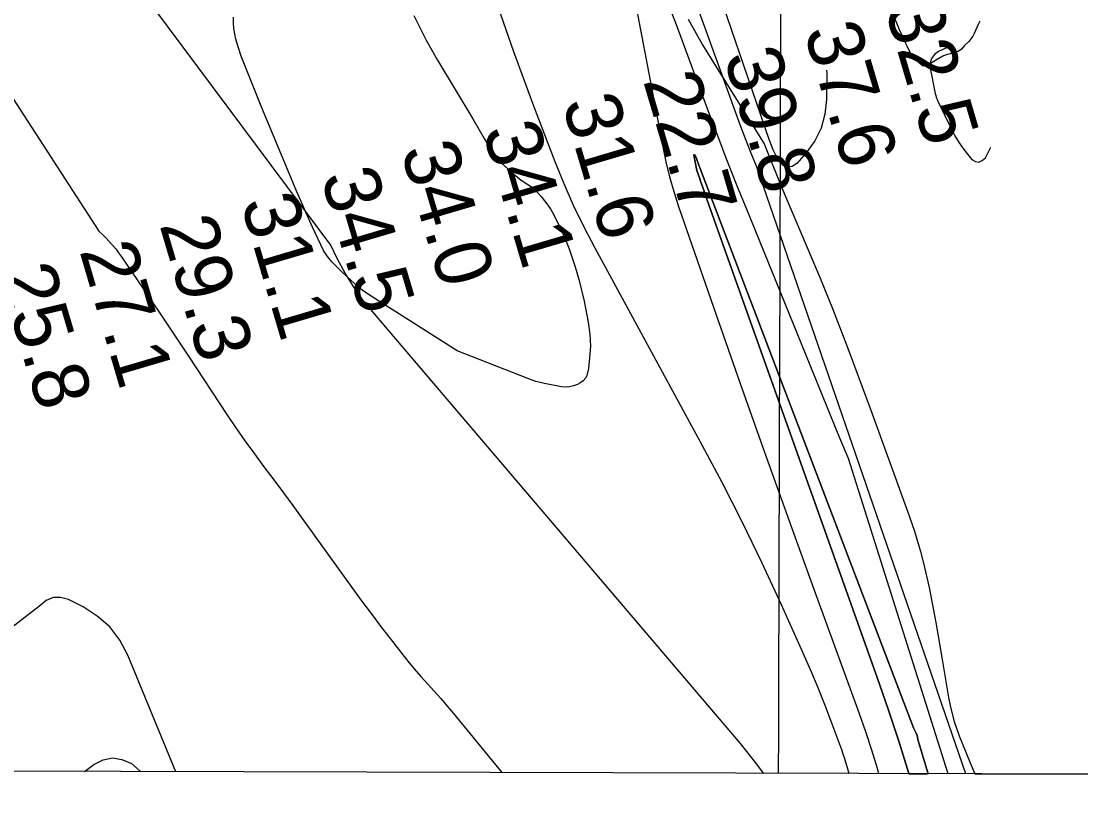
# Model space of a CAD drawing. Extents: x 3161665 to 3199565, y 885729 to 911164.
# Drawn here: x 3180653 to 3181912, y 891109 to 892047 of the extents above; entities that cross this region are included whole.
import ezdxf

# ---------------------------------------------------------------- set-up
doc = ezdxf.new("R2010")
doc.units = 0
for name, color, linetype in [('V-GRID-FRAM', 7, 'Continuous'), ('V-GRID-MAJR', 7, 'Continuous'), ('V-RIVR-RANG', 7, 'Continuous'), ('V-SITE-VEGE', 7, 'Continuous'), ('V-TOPO-DPTH', 7, 'Continuous'), ('V-TOPO-MAJR', 7, 'Continuous'), ('V-TOPO-MINR', 7, 'Continuous'), ('V-TOPO-SHOR', 7, 'Continuous')]:
    doc.layers.add(name, color=color, linetype=linetype)

msp = doc.modelspace()

# ---------------------------------------------------------------- linework, layer by layer
at = {"layer": 'V-GRID-FRAM'}
msp.add_lwpolyline([(3165935.6, 909383.8), (3197271.3, 909297.2), (3197229, 891108.8), (3165877.4, 891195.5), (3165935.6, 909383.8)], dxfattribs=at)
at = {"layer": 'V-GRID-MAJR'}
msp.add_spline([(3181553.2, 891152.2), (3181570, 897211.5), (3181586.7, 903274.3), (3181603.5, 909337.1), (3181603.5, 909340.5)], degree=3, dxfattribs=at)
at = {"layer": 'V-SITE-VEGE'}
for p, q in [((3181693.8, 892044.4), (3181688.8, 892055.5)), ((3181445.5, 892049.3), (3181462.5, 892018.8)), ((3181697.9, 892034.4), (3181693.8, 892044.4)), ((3181790.1, 892042.2), (3181786.1, 892032.9)), ((3181792.5, 892046.9), (3181790.1, 892042.2)), ((3181701.5, 892026.9), (3181697.9, 892034.4)), ((3181703.2, 892023.6), (3181701.5, 892026.9)), ((3181784, 892029), (3181779.4, 892022.7)), ((3181786.1, 892032.9), (3181784, 892029)), ((3181462.5, 892018.8), (3181472.9, 892001.8)), ((3181704.4, 892020.3), (3181703.2, 892023.6)), ((3181705.9, 892017), (3181704.4, 892020.3)), ((3181710, 892008.9), (3181705.9, 892017)), ((3181774.3, 892017.7), (3181770.7, 892013.5)), ((3181779.4, 892022.7), (3181774.3, 892017.7)), ((3181472.9, 892001.8), (3181536.1, 891901)), ((3181712.4, 892005.8), (3181710, 892008.9)), ((3181714.5, 892002.8), (3181712.4, 892005.8)), ((3181717.8, 891999.2), (3181714.5, 892002.8)), ((3181748.4, 892005), (3181740.9, 892000.8)), ((3181751.4, 892006.4), (3181748.4, 892005)), ((3181757.1, 892007.9), (3181751.4, 892006.4)), ((3181760.1, 892009.1), (3181757.1, 892007.9)), ((3181766.8, 892010.8), (3181760.1, 892009.1)), ((3181770.7, 892013.5), (3181766.8, 892010.8)), ((3181721.3, 891995.9), (3181717.8, 891999.2)), ((3181724.9, 891993.4), (3181721.3, 891995.9)), ((3181729.4, 891994.3), (3181724.9, 891993.4)), ((3181732.7, 891995.5), (3181729.4, 891994.3)), ((3181740.9, 892000.8), (3181732.7, 891995.5)), ((3181536.1, 891901), (3181557.2, 891848.5)), ((3181557.2, 891848.5), (3181602.6, 891741.1)), ((3181602.6, 891741.1), (3181617.1, 891705)), ((3181617.1, 891705), (3181635.7, 891656.8)), ((3181635.7, 891656.8), (3181662.8, 891584)), ((3181662.8, 891584), (3181706.5, 891464)), ((3181706.5, 891464), (3181714.6, 891440.3)), ((3181714.6, 891440.3), (3181721.9, 891416.2)), ((3181721.9, 891416.2), (3181726, 891400.6)), ((3181726, 891400.6), (3181732.2, 891373.1)), ((3181732.2, 891373.1), (3181740, 891331.6)), ((3181740, 891331.6), (3181747.2, 891290)), ((3181747.2, 891290), (3181755, 891242.3)), ((3181755, 891242.3), (3181757.5, 891230.8)), ((3181757.5, 891230.8), (3181762.1, 891213.7)), ((3181762.1, 891213.7), (3181767.9, 891197)), ((3181767.9, 891197), (3181780.8, 891164.8)), ((3181780.8, 891164.8), (3181786.4, 891151.5)), ((3181786.4, 891151.5), (3182625.4, 891149.2))]:
    msp.add_line(p, q, dxfattribs=at)
for points in [[(3181119.6, 892053.6), (3181127.2, 892037.7), (3181134.3, 892024), (3181147.7, 892000.4)], [(3181322.1, 891713.8), (3181326.9, 891688.7), (3181328.8, 891674.6), (3181329.4, 891660.4), (3181328.9, 891651.2), (3181328.1, 891642), (3181327.1, 891633.7), (3181325.1, 891625.4), (3181323.8, 891622.7), (3181320.8, 891619.2), (3181316.9, 891616.3), (3181313.9, 891614.6), (3181309.3, 891612.9), (3181304.6, 891611.9), (3181299.7, 891611.5), (3181294.9, 891611.7), (3181274.7, 891615.7), (3181264.7, 891618.3), (3181255, 891621.7), (3181171.1, 891654.9), (3181064.4, 891722.5), (3181056.2, 891728.3), (3181044.9, 891738.3), (3181034, 891748.8), (3181022, 891760.6), (3181016.7, 891767), (3181012.2, 891774.1), (3180998.8, 891801.8), (3180980.2, 891843.8), (3180938.1, 891945.5), (3180914.3, 892005.1), (3180910.9, 892015.1), (3180908, 892025.3), (3180906.6, 892031.6), (3180905.6, 892037.9), (3180905.1, 892044.7), (3180905, 892051.6)], [(3181147.7, 892000.4), (3181189.8, 891930.7), (3181203.2, 891907.3), (3181210.3, 891895.7), (3181217.9, 891884.5), (3181223.8, 891878), (3181238.4, 891864.7), (3181246.9, 891857.6), (3181260.5, 891849), (3181265.9, 891843.8), (3181270.8, 891838.1), (3181278.6, 891828), (3181282.2, 891822.8), (3181285.4, 891817.2), (3181293.1, 891801.7), (3181299.2, 891788.1), (3181304, 891776), (3181311.4, 891754.7), (3181316.1, 891738.5), (3181322.1, 891713.8)]]:
    msp.add_lwpolyline(points, dxfattribs=at)
at = {"layer": 'V-TOPO-DPTH'}
for points in [[(3181462.6, 891850), (3181460.8, 891855.3), (3181459, 891860.6), (3181456.1, 891869.1), (3181455.5, 891871.2), (3181455, 891873.3), (3181452.3, 891887.5), (3181452.5, 891887.8), (3181452.7, 891888.1), (3181452.9, 891888), (3181453.3, 891887.8), (3181454, 891886.5), (3181455.4, 891883.7), (3181456, 891882.2), (3181458.9, 891874.5), (3181459.3, 891873.5), (3181460.1, 891871.4), (3181460.5, 891870.3), (3181713.7, 891206.5), (3181714.1, 891205.7), (3181714.7, 891204.1), (3181716.6, 891200.1), (3181718, 891197.2), (3181718.4, 891195.3), (3181718.9, 891192.3), (3181719.9, 891188.4), (3181730.9, 891151.7)], [(3181730.9, 891151.7), (3181719.9, 891188.4), (3181718.9, 891192.3), (3181718.4, 891195.3), (3181718, 891197.2), (3181716.6, 891200.1), (3181714.7, 891204.1), (3181714.1, 891205.7), (3181713.7, 891206.5), (3181460.5, 891870.3), (3181460.1, 891871.4), (3181459.3, 891873.5), (3181458.9, 891874.5), (3181456, 891882.2), (3181455.4, 891883.7), (3181454, 891886.5), (3181453.3, 891887.8), (3181452.9, 891888), (3181452.7, 891888.1), (3181452.5, 891887.8), (3181452.3, 891887.5), (3181455, 891873.3), (3181455.5, 891871.2), (3181456.1, 891869.1), (3181459, 891860.6), (3181460.8, 891855.3), (3181462.6, 891850)], [(3181730.9, 891151.7), (3181708, 891151.7), (3181707.9, 891152), (3181696.1, 891190.3), (3181683.6, 891228.4), (3181670.5, 891266.3), (3181466.3, 891839.5), (3181464.5, 891844.7), (3181462.6, 891850)], [(3181462.6, 891850), (3181464.5, 891844.7), (3181466.3, 891839.5), (3181670.5, 891266.3), (3181683.6, 891228.4), (3181696.1, 891190.3), (3181707.9, 891152), (3181708, 891151.7), (3181730.9, 891151.7)]]:
    msp.add_lwpolyline(points, dxfattribs=at)
at = {"layer": 'V-TOPO-MAJR'}
msp.add_lwpolyline([(3181610.3, 891988.4), (3181610.4, 891985.1), (3181610.2, 891953.5), (3181608.2, 891936.1), (3181603.9, 891919.6), (3181596.1, 891904.3), (3181586, 891890), (3181575, 891877.4), (3181569.1, 891874.1), (3181563.5, 891873.1), (3181558.3, 891875.5), (3181553.5, 891880.3), (3181548.8, 891889.9), (3181546.9, 891893.9), (3181545.1, 891897.9), (3181543.5, 891902), (3181542, 891906.2), (3181367, 892416.9), (3181343.1, 892486.4), (3181319.1, 892555.9)], dxfattribs=at)
at = {"layer": 'V-TOPO-MINR'}
for points in [[(3181775.7, 891151.5), (3181526.9, 891874.2), (3181520.2, 891890.5), (3181513.8, 891906.9), (3181507.6, 891923.4), (3181421.8, 892160.7), (3181395.1, 892231.3), (3181147.5, 892778.3)], [(3181535.8, 891152.2), (3181525.7, 891165), (3181507.9, 891187.8), (3181070.4, 891701.4), (3181058.4, 891715.9), (3181047.7, 891731.3), (3181037.7, 891747.1), (3181028.8, 891763.6), (3181020.6, 891780.5), (3180544.9, 892418.5)], [(3180363.9, 892385.2), (3180744.9, 891797.1), (3180749.1, 891793), (3180753.3, 891788.9), (3180757.3, 891784.7), (3180761.2, 891780.4), (3180765, 891776), (3180768.5, 891771.3), (3180771.9, 891766.6), (3180803.8, 891719.5), (3180815.7, 891701.7), (3180827.7, 891684), (3180839.5, 891666.1), (3180851.4, 891648.3), (3180897.1, 891579.1), (3180907.8, 891563.3), (3180918.7, 891547.6), (3180929.9, 891532.1), (3180941.3, 891516.7), (3180952.8, 891501.4), (3180964.3, 891486), (3180975.6, 891470.6), (3180986.8, 891455.1), (3181043.9, 891376), (3181056.2, 891359.1), (3181068.6, 891342.3), (3181081.2, 891325.7), (3181094, 891309.1), (3181105.1, 891294.7), (3181112.5, 891285.5), (3181120, 891276.4), (3181127.7, 891267.5), (3181135.6, 891258.8), (3181143.6, 891250.1), (3181151.4, 891241.3)], [(3181370.7, 892132.6), (3181415.4, 891897.4), (3181419.2, 891879.5), (3181423.6, 891861.6), (3181428.7, 891844), (3181434.3, 891826.5), (3181479, 891697.6), (3181507.6, 891615.8), (3181536.4, 891534.1), (3181565.7, 891452.6), (3181595.1, 891371.1), (3181648.9, 891223.4), (3181656.5, 891201.8), (3181663.7, 891180.1), (3181670.3, 891158.2), (3181672.1, 891151.8)], [(3181216.5, 892072.5), (3181238, 892010.7), (3181260.5, 891949.3), (3181287, 891880), (3181297.7, 891853.7), (3181309, 891827.8), (3181321.4, 891802.3), (3181334.5, 891777.1), (3181459.7, 891547.2), (3181485.1, 891499.3), (3181509.7, 891451.1), (3181533.3, 891402.4), (3181556.1, 891353.2), (3181582.1, 891295.5), (3181591.1, 891274.9), (3181599.8, 891254.2), (3181608.1, 891233.3), (3181616.2, 891212.2), (3181627.8, 891180.7), (3181629.7, 891175.3), (3181631.5, 891169.9), (3181633.2, 891164.5), (3181634.7, 891159), (3181636.6, 891151.9)], [(3181754.9, 891151.6), (3181636.1, 891526.8), (3181625.8, 891550.9), (3181515.7, 891821.9), (3181503.7, 891851.9), (3181491.8, 891882), (3181480.2, 891912.3), (3181468.8, 891942.5), (3181430.6, 892045.6), (3181421, 892069.5)], [(3181756.3, 892016.7), (3181743.3, 892010.7), (3181738.4, 892007), (3181734.8, 892002.5), (3181733.4, 891997), (3181733.3, 891990.8), (3181739.5, 891960.8), (3181740, 891958.5), (3181740.7, 891956.2), (3181742.5, 891951.8), (3181758.2, 891919), (3181762.7, 891910.3), (3181767.7, 891902), (3181773.4, 891894.1), (3181779.5, 891886.5), (3181783, 891882.4), (3181787.3, 891879.9), (3181791.4, 891879.1), (3181795.3, 891880.9), (3181799, 891884.3), (3181805.6, 891896.8)], [(3181462.6, 891850), (3181460.8, 891855.3), (3181459, 891860.6), (3181456.1, 891869.1), (3181455.5, 891871.2), (3181455, 891873.3), (3181452.3, 891887.5), (3181452.5, 891887.8), (3181452.7, 891888.1), (3181452.9, 891888), (3181453.3, 891887.8), (3181454, 891886.5), (3181455.4, 891883.7), (3181456, 891882.2), (3181458.9, 891874.5), (3181459.3, 891873.5), (3181460.1, 891871.4), (3181460.5, 891870.3), (3181713.7, 891206.5), (3181714.1, 891205.7), (3181714.7, 891204.1), (3181716.6, 891200.1), (3181718, 891197.2), (3181718.4, 891195.3), (3181718.9, 891192.3), (3181719.9, 891188.4), (3181730.9, 891151.7)], [(3181708, 891151.7), (3181707.9, 891152), (3181696.1, 891190.3), (3181683.6, 891228.4), (3181670.5, 891266.3), (3181466.3, 891839.5), (3181464.5, 891844.7), (3181462.6, 891850)], [(3180836.6, 891154.1), (3180779.5, 891292.8), (3180769.8, 891310.5), (3180758, 891326.4), (3180743.1, 891339.3), (3180726.1, 891350.3), (3180708.9, 891359), (3180699.4, 891361.4), (3180690.5, 891361.4), (3180682.3, 891357.7), (3180674.6, 891351.6), (3180494.7, 891212.8)], [(3181151.4, 891241.3), (3181159.1, 891232.3), (3181166.6, 891223.3), (3181224.2, 891153.1)], [(3180728, 891154.4), (3180739, 891162.9), (3180750.1, 891168.3), (3180761.2, 891170.8), (3180772.4, 891168.8), (3180783.7, 891163.8), (3180794.1, 891154.9), (3180794.8, 891154.3)]]:
    msp.add_lwpolyline(points, dxfattribs=at)
at = {"layer": 'V-TOPO-SHOR'}
msp.add_lwpolyline([(3181792.5, 892046.9), (3181790.1, 892042.2), (3181786.1, 892032.9), (3181784, 892029), (3181779.4, 892022.7), (3181774.3, 892017.7), (3181770.7, 892013.5), (3181766.8, 892010.8), (3181760.1, 892009.1), (3181757.1, 892007.9), (3181751.4, 892006.4), (3181748.4, 892005), (3181740.9, 892000.8), (3181732.7, 891995.5), (3181729.4, 891994.3), (3181724.9, 891993.4), (3181721.3, 891995.9), (3181717.8, 891999.2), (3181714.5, 892002.8), (3181712.4, 892005.8), (3181710, 892008.9), (3181705.9, 892017), (3181704.4, 892020.3), (3181703.2, 892023.6), (3181701.5, 892026.9), (3181697.9, 892034.4), (3181693.8, 892044.4), (3181688.8, 892055.5)], dxfattribs=at)

# ---------------------------------------------------------------- texts
at = {"layer": 'V-RIVR-RANG'}
for s, p in [('32.5', (3181679.3, 892061.8)), ('37.6', (3181582.9, 892035)), ('39.8', (3181487.6, 892004.7)), ('22.7', (3181391.8, 891976.1)), ('31.6', (3181295.4, 891949.3)), ('34.1', (3181200.8, 891916.7)), ('34.0', (3181103.5, 891893.2)), ('34.5', (3181008.5, 891861.8)), ('31.1', (3180913.3, 891831)), ('29.3', (3180816.8, 891804.7)), ('27.1', (3180721.6, 891773.9)), ('25.8', (3180625.1, 891747.6))]:
    msp.add_text(s, height=67, rotation=286.4583, dxfattribs=at).set_placement(p)

doc.saveas('drawing.dxf')
